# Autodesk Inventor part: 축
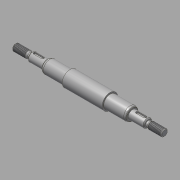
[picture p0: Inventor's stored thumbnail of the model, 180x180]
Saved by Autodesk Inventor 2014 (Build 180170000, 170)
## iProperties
Created: 2015-11
Part Number: 축
Material: 강철, 연강
Document SubType Name: Modeling
Designer: mduedu
Density: 1 g/cm^3
Appearance: 강철
Author: mduedu
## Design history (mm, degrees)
sketch "스케치1"
  geometry: L1 (-86, 0)-(86, 0); L2 (-86, 0)-(-86, 4); L3 (-86, 4)-(-70.732, 4); L4 (-70.732, 4)-(-69, 3); L5 (-69, 3)-(-67, 3); L6 (-67, 3)-(-67, 5); L7 (-67, 5)-(-49, 5); L8 (-49, 5)-(-49, 6.55); L9 (-47.355, 7.5)-(-23, 7.5); L10 (-23, 7.5)-(-23, 9); L11 (0, 0)-(0, 9); L12 (86, 4)-(70.732, 4); L13 (70.732, 4)-(69, 3); L14 (69, 3)-(67, 3); L15 (67, 3)-(67, 5); L16 (67, 5)-(49, 5); L17 (23, 7.5)-(23, 9); L18 (86, 0)-(86, 4); L19 (-23, 9)-(23, 9); L20 (-49, 6.55)-(-47.355, 7.5); L21 (47.355, 7.5)-(23, 7.5); L22 (49, 6.55)-(47.355, 7.5); L23 (49, 5)-(49, 6.55); 1 further point
  constraints: 46 end point, 10 symmetric about line, 6 perpendicular, 5 parallel, 2 midpoint, 1 coincident, 1 horizontal
  dimensions: "d0" = 172 distance of L1.start L1.end (derived); "d1" = 8 diameter of L3 L1; "d2" = 30 deg angle of L4 L5; "d3" = 6 diameter of L5 L1; "d4" = 10 diameter of L7 L1; "d5" = 15 diameter of L9 L1; "d6" = 18 diameter of L19 L1; "d8" = 18 distance of L6.end L7.end; "d9" = 46 distance of L10.end L17.end; "d10" = 2 distance of L4.end L5.end; "d11" = 17 distance from line of L4.end L2; "d16" = 13.1 diameter of L8.end L1; "d17" = 30 deg angle of L20 L9; "d18" = 26 distance between parallel lines of L10 L8
revolve "회전1" sketch "스케치1" stored, may be unused: angle "d12" = 90 deg
chamfer "모따기1" distance "d13" = 1; stored, may be unused: second distance "d14" = 2, angle "d15" = 45 deg
fillet "모깎기1" dims "d19" = 4, "d20" = 0.5
node "작업 평면1"
sketch "스케치2" dims "d23" = 12
  geometry: L1 (-5.5, 1.5)-(3.5, 1.5); L2 (3.5, 1.5)-(3.5, -1.5); L3 (3.5, -1.5)-(-5.5, -1.5); L4 (-5.5, -1.5)-(-5.5, 1.5); L5 (-9, -4)-(-9, 4) reference; 3 further points
  constraints: 8 end point, 2 midpoint, 2 parallel, 2 vertical alignment, 1 horizontal, 1 perpendicular, 4 other
  dimensions: "d21" = 3 distance between parallel lines of L3 L1; "d24" = 2 dimension on L5
extrude "돌출1" cut sketch "스케치2" distance "d25" = 1.8; taper "d26" = 0 deg
feature "스레드1" dims "d27" = 10, "d28" = 0
feature "스레드2" dims "d29" = 10, "d30" = 0
chamfer "모따기2" distance "d31" = 1; stored, may be unused: second distance "d32" = 2, angle "d33" = 45 deg
fillet "모깎기2" dims "d34" = 0.3
node "솔리드1"
mirror "대칭1"
